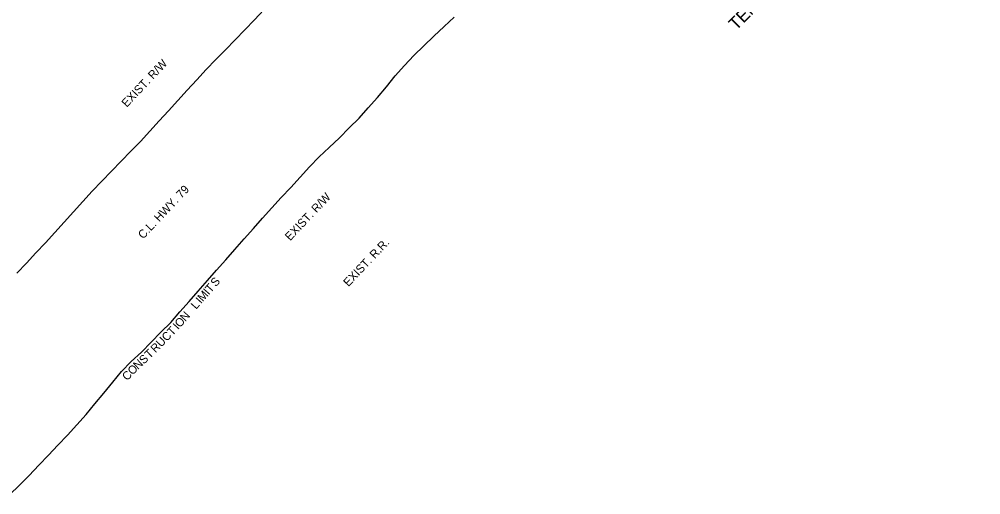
# Model space of a CAD drawing. Extents: x 1377291 to 1378879, y 1932405 to 1934097.
# Drawn here: x 1378187 to 1378879, y 1932883 to 1933226 of the extents above; entities that cross this region are included whole.
import ezdxf

# ---------------------------------------------------------------- set-up
doc = ezdxf.new("R2010")
doc.units = 0
for name, color, linetype in [('60', 7, 'Continuous'), ('R_Draft', 7, 'Continuous'), ('R_NO PLOT', 7, 'Continuous')]:
    doc.layers.add(name, color=color, linetype=linetype)

msp = doc.modelspace()

# ---------------------------------------------------------------- linework, layer by layer
at = {"layer": 'R_NO PLOT'}
for points in [[(1378363.52, 1933232.79), (1378356.74, 1933225.43), (1378349.75, 1933218.28), (1378342.75, 1933211.14), (1378335.76, 1933203.98), (1378328.76, 1933196.83), (1378321.81, 1933189.64), (1378315.09, 1933182.24), (1378308.36, 1933174.83), (1378301.62, 1933167.45), (1378294.87, 1933160.07), (1378288.14, 1933152.68), (1378281.39, 1933145.29), (1378274.54, 1933138.01), (1378267.58, 1933130.82), (1378260.63, 1933123.64), (1378253.67, 1933116.45), (1378246.71, 1933109.27), (1378239.75, 1933102.08), (1378233.07, 1933094.64), (1378226.41, 1933087.18), (1378219.74, 1933079.72), (1378213.03, 1933072.31), (1378206.19, 1933065.01), (1378199.37, 1933057.7), (1378192.54, 1933050.39), (1378185.72, 1933043.08)], [(1378180.26, 1932883.49), (1378187.46, 1932890.44), (1378194.57, 1932897.48), (1378201.45, 1932904.74), (1378208.34, 1932911.99), (1378215.24, 1932919.23), (1378222.14, 1932926.47), (1378228.94, 1932933.8), (1378235.49, 1932941.37), (1378241.89, 1932949.07), (1378248.34, 1932956.73), (1378254.65, 1932964.53), (1378260.99, 1932972.29), (1378267.97, 1932979.46), (1378275.31, 1932986.28), (1378282.4, 1932993.35), (1378289.4, 1933000.49), (1378296.39, 1933007.64), (1378303, 1933015.16), (1378309.59, 1933022.68), (1378316.21, 1933030.18), (1378322.77, 1933037.74), (1378329.39, 1933045.24), (1378336.03, 1933052.72), (1378342.65, 1933060.23), (1378349.26, 1933067.74), (1378355.89, 1933075.23), (1378362.52, 1933082.73), (1378369.25, 1933090.12), (1378376.02, 1933097.48), (1378382.78, 1933104.86), (1378389.52, 1933112.24), (1378396.27, 1933119.62), (1378403.29, 1933126.75), (1378410.55, 1933133.65), (1378417.77, 1933140.59), (1378424.8, 1933147.7), (1378431.98, 1933154.68), (1378438.62, 1933162.16), (1378445.26, 1933169.64), (1378451.79, 1933177.22), (1378458.05, 1933185.07), (1378464.59, 1933192.65), (1378471.49, 1933199.89), (1378478.65, 1933206.88), (1378485.82, 1933213.86), (1378493.15, 1933220.69), (1378500.49, 1933227.52)]]:
    msp.add_lwpolyline(points, dxfattribs=at)

# ---------------------------------------------------------------- texts
at = {"layer": '60'}
msp.add_text('TEMPORARY EROSION CONTROL DETAILS', height=9, rotation=45, dxfattribs=at).set_placement((1378703.39, 1933217.45))
at = {"layer": 'R_Draft'}
for s, rotation, p in [('EXIST. R/W', 46.66069, (1378264.76, 1933162.16)), ('C.L. HWY. 79', 46.66069, (1378276.55, 1933067.28)), ('EXIST. R/W', 46.66069, (1378382.36, 1933066)), ('EXIST. R.R.', 46.66069, (1378424.31, 1933032.96)), ('S', 48.54385, (1378328.91, 1933032.91)), ('M', 48.55709, (1378319.54, 1933022.17)), ('I', 49.03456, (1378323.8, 1933027.03)), ('T', 49.03456, (1378325.11, 1933028.53)), ('I', 48.55709, (1378318.22, 1933020.68)), ('L', 48.55709, (1378314.66, 1933016.64)), ('O', 48.66173, (1378303.11, 1933003.47)), ('N', 48.66173, (1378306.98, 1933007.87)), ('T', 45.66202, (1378297.46, 1932997.58)), ('I', 48.66173, (1378301.8, 1933001.98)), ('U', 45.57718, (1378289.46, 1932989.41)), ('C', 45.66202, (1378293.5, 1932993.53)), ('R', 44.91105, (1378285.41, 1932985.34)), ('S', 42.90619, (1378276.98, 1932977.18)), ('T', 44.91105, (1378281.26, 1932981.2)), ('O', 45.78195, (1378268.98, 1932969.31)), ('N', 42.90619, (1378272.82, 1932973.32)), ('C', 45.78195, (1378265.02, 1932965.25))]:
    msp.add_text(s, height=6, rotation=rotation, dxfattribs=at).set_placement(p)

doc.saveas('drawing.dxf')
